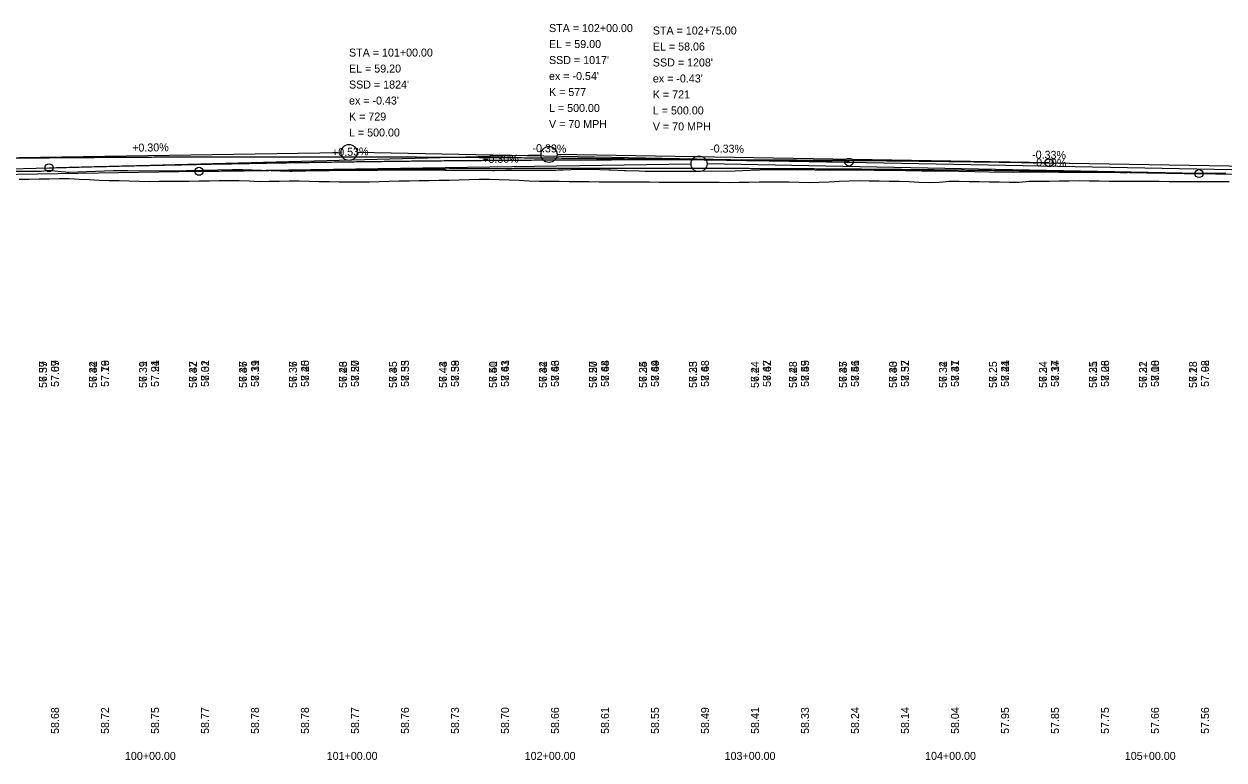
# Model space of a CAD drawing. Extents: x 3880794 to 3915434, y 287517 to 300173.
# Drawn here: x 3890476 to 3891076, y 296520 to 296888 of the extents above; entities that cross this region are included whole.
import ezdxf

# ---------------------------------------------------------------- set-up
doc = ezdxf.new("R2010")
doc.units = 0
for name, color, linetype in [('Level 1', 7, 'Continuous'), ('Level 2', 7, 'Continuous'), ('Level 30', 7, 'Continuous'), ('Level 31', 7, 'Continuous'), ('Level 32', 7, 'Continuous')]:
    doc.layers.add(name, color=color, linetype=linetype)

msp = doc.modelspace()

# ---------------------------------------------------------------- linework, layer by layer
at = {"layer": 'Level 1'}
for p, q in [((3890388.3, 296820.01), (3890634.3, 296823.7)), ((3890488.3, 296816.09), (3890734.3, 296822.65)), ((3890888.3, 296818.94), (3890642.3, 296823.68)), ((3890988.3, 296818.59), (3890742.3, 296822.69)), ((3890438.3, 296814.76), (3890488.3, 296816.09)), ((3890888.3, 296818.94), (3891088.3, 296815.08)), ((3890988.3, 296818.59), (3891088.3, 296816.92))]:
    msp.add_line(p, q, dxfattribs=at)
for points in [[(3890470.64, 296814.38), (3890481.24, 296814.49), (3890481.57, 296814.49), (3890484.41, 296814.33), (3890485.66, 296814.55), (3890487.25, 296814.72), (3890489.34, 296814.66), (3890491.17, 296814.52), (3890494.38, 296814.25), (3890496.56, 296814.04), (3890497.6, 296813.93), (3890498.03, 296813.87), (3890520.48, 296814.73), (3890526.64, 296814.75), (3890527.58, 296814.74), (3890552.38, 296814.64), (3890556.96, 296814.73)], [(3890556.96, 296814.73), (3890558.17, 296814.73), (3890580.05, 296815.22), (3890582.32, 296815.25), (3890585.1, 296815.18), (3890608.88, 296814.47), (3890609.81, 296814.49), (3890615.66, 296814.58), (3890616.57, 296814.56), (3890640.14, 296814.94), (3890641.21, 296814.92), (3890651.51, 296814.96), (3890652.48, 296814.96), (3890676.43, 296815.05), (3890677.22, 296815.06), (3890685.45, 296814.98), (3890686.13, 296815), (3890686.43, 296814.99), (3890710.09, 296814.78), (3890710.44, 296814.79), (3890710.81, 296814.82), (3890716.71, 296814.84), (3890717.43, 296814.85), (3890728.83, 296814.88), (3890729.73, 296814.9), (3890731.14, 296814.94), (3890741.66, 296814.97), (3890743.03, 296815.01), (3890745.42, 296815.06), (3890753.04, 296815.41), (3890759.14, 296815.39), (3890768.18, 296815.06), (3890768.97, 296815.03), (3890775.95, 296814.78), (3890776.75, 296814.71), (3890783.31, 296814.54), (3890786.37, 296814.45), (3890794.24, 296814.42), (3890798.91, 296814.46), (3890805.76, 296814.47), (3890812.3, 296814.49), (3890819.03, 296814.52), (3890827.49, 296814.44), (3890838.93, 296814.96), (3890848.37, 296815.21), (3890862.69, 296815.16), (3890864.24, 296815.19), (3890878.37, 296814.98), (3890886.25, 296815.03), (3890900.83, 296814.83), (3890908.36, 296814.83), (3890908.78, 296814.83), (3890924.72, 296814.64), (3890933.63, 296814.51), (3890934.62, 296814.5), (3890951.3, 296814.31), (3890958.54, 296814.07), (3890970.52, 296813.95), (3890978.52, 296814.02), (3890993.25, 296813.91), (3891001.84, 296813.88), (3891007.06, 296813.85), (3891023.83, 296813.73), (3891027.36, 296813.73), (3891030.67, 296813.85), (3891046.08, 296813.75), (3891051.84, 296813.42), (3891067.15, 296813.41), (3891071.65, 296813.43), (3891076.77, 296813.34)]]:
    msp.add_lwpolyline(points, dxfattribs=at)
for centre in [(3890638.3, 296823.76), (3890738.3, 296822.76)]:
    msp.add_circle(centre, 4, dxfattribs=at)
for points in [[(3890388.3, 296820.01), (3890398.3, 296820.15), (3890408.3, 296820.29), (3890418.3, 296820.43), (3890428.3, 296820.55), (3890438.3, 296820.67), (3890448.3, 296820.78), (3890458.3, 296820.89), (3890468.3, 296820.99), (3890478.3, 296821.08), (3890488.3, 296821.16), (3890498.3, 296821.24), (3890508.3, 296821.31), (3890518.3, 296821.38), (3890528.3, 296821.43), (3890538.3, 296821.49), (3890548.3, 296821.53), (3890558.3, 296821.57), (3890568.3, 296821.6), (3890578.3, 296821.62), (3890588.3, 296821.64), (3890598.3, 296821.64), (3890608.3, 296821.65), (3890618.3, 296821.64), (3890628.3, 296821.63), (3890638.3, 296821.61), (3890648.3, 296821.59), (3890658.3, 296821.56), (3890668.3, 296821.52), (3890678.3, 296821.47), (3890688.3, 296821.42), (3890698.3, 296821.36), (3890708.3, 296821.3), (3890718.3, 296821.22), (3890728.3, 296821.14), (3890738.3, 296821.06), (3890748.3, 296820.96), (3890758.3, 296820.86), (3890768.3, 296820.76), (3890778.3, 296820.64), (3890788.3, 296820.52), (3890798.3, 296820.39), (3890808.3, 296820.26), (3890818.3, 296820.12), (3890828.3, 296819.97), (3890838.3, 296819.81), (3890848.3, 296819.65), (3890858.3, 296819.48), (3890868.3, 296819.31), (3890878.3, 296819.12), (3890888.3, 296818.94)], [(3890488.3, 296816.09), (3890498.3, 296816.35), (3890508.3, 296816.61), (3890518.3, 296816.85), (3890528.3, 296817.09), (3890538.3, 296817.32), (3890548.3, 296817.53), (3890558.3, 296817.74), (3890568.3, 296817.95), (3890578.3, 296818.14), (3890588.3, 296818.32), (3890598.3, 296818.5), (3890608.3, 296818.67), (3890618.3, 296818.82), (3890628.3, 296818.97), (3890638.3, 296819.12), (3890648.3, 296819.25), (3890658.3, 296819.37), (3890668.3, 296819.49), (3890678.3, 296819.59), (3890688.3, 296819.69), (3890698.3, 296819.78), (3890708.3, 296819.86), (3890718.3, 296819.93), (3890728.3, 296819.99), (3890738.3, 296820.05), (3890748.3, 296820.09), (3890758.3, 296820.13), (3890768.3, 296820.16), (3890778.3, 296820.18), (3890788.3, 296820.19), (3890798.3, 296820.19), (3890808.3, 296820.19), (3890818.3, 296820.17), (3890828.3, 296820.15), (3890838.3, 296820.12), (3890848.3, 296820.07), (3890858.3, 296820.02), (3890868.3, 296819.97), (3890878.3, 296819.9), (3890888.3, 296819.82), (3890898.3, 296819.74), (3890908.3, 296819.65), (3890918.3, 296819.54), (3890928.3, 296819.43), (3890938.3, 296819.32), (3890948.3, 296819.19), (3890958.3, 296819.05), (3890968.3, 296818.91), (3890978.3, 296818.75), (3890988.3, 296818.59)]]:
    msp.add_spline(points, degree=3, dxfattribs=at)
at = {"layer": 'Level 2'}
for p, q in [((3890438.3, 296812.46), (3890563.3, 296814.33)), ((3890563.3, 296814.33), (3890809.3, 296818.02)), ((3891063.3, 296813.17), (3890817.3, 296818)), ((3891063.3, 296813.17), (3891088.3, 296812.67))]:
    msp.add_line(p, q, dxfattribs=at)
for points in [[(3890473.3, 296810.35), (3890478.3, 296810.39), (3890483.3, 296810.5), (3890488.3, 296810.61), (3890493.3, 296810.72), (3890498.3, 296810.77), (3890503.3, 296810.47), (3890508.3, 296810.17), (3890513.3, 296809.88), (3890518.3, 296809.79), (3890523.3, 296809.66), (3890528.3, 296809.53), (3890533.3, 296809.4), (3890538.3, 296809.31)], [(3890538.3, 296809.31), (3890543.3, 296809.35), (3890548.3, 296809.4), (3890553.3, 296809.44), (3890558.3, 296809.48), (3890563.3, 296809.59), (3890568.3, 296809.65), (3890573.3, 296809.7), (3890578.3, 296809.75), (3890583.3, 296809.81), (3890588.3, 296809.59), (3890593.3, 296809.25), (3890598.3, 296809.45), (3890603.3, 296809.48), (3890608.3, 296809.57), (3890613.3, 296809.59), (3890618.3, 296809.41), (3890623.3, 296809.32), (3890628.3, 296809.23), (3890633.3, 296809.14), (3890638.3, 296809.07), (3890643.3, 296809.09), (3890648.3, 296809.12), (3890653.3, 296809.2), (3890658.3, 296809.39), (3890663.3, 296809.5), (3890668.3, 296809.61), (3890673.3, 296809.66), (3890678.3, 296809.74), (3890683.3, 296809.83), (3890688.3, 296809.9), (3890693.3, 296810.04), (3890698.3, 296810.22), (3890703.3, 296810.39), (3890708.3, 296810.4), (3890713.3, 296810.26), (3890718.3, 296810.06), (3890723.3, 296809.83), (3890728.3, 296809.62), (3890733.3, 296809.45), (3890738.3, 296809.35), (3890743.3, 296809.33), (3890748.3, 296809.31), (3890753.3, 296809.18), (3890758.3, 296809.16), (3890763.3, 296809.13), (3890768.3, 296809.13), (3890773.3, 296809.13), (3890778.3, 296809.15), (3890783.3, 296809.09), (3890788.3, 296809.02), (3890793.3, 296808.95), (3890798.3, 296808.96), (3890803.3, 296808.96), (3890808.3, 296808.89), (3890813.3, 296808.9), (3890818.3, 296808.9), (3890823.3, 296808.91), (3890828.3, 296808.82), (3890833.3, 296808.89), (3890838.3, 296808.97), (3890843.3, 296809.04), (3890848.3, 296809.15), (3890853.3, 296809.1), (3890858.3, 296809), (3890863.3, 296808.9), (3890868.3, 296808.81), (3890873.3, 296808.9), (3890878.3, 296809.13), (3890883.3, 296809.36), (3890888.3, 296809.6), (3890893.3, 296809.73), (3890898.3, 296809.65), (3890903.3, 296809.56), (3890908.3, 296809.47), (3890913.3, 296809.38), (3890918.3, 296809.31), (3890923.3, 296808.94), (3890928.3, 296808.72), (3890933.3, 296808.87), (3890938.3, 296809.38), (3890943.3, 296809.36), (3890948.3, 296809.29), (3890953.3, 296809.2), (3890958.3, 296809.1), (3890963.3, 296809), (3890968.3, 296808.89), (3890973.3, 296808.95), (3890978.3, 296809.38), (3890983.3, 296809.42), (3890988.3, 296809.46), (3890993.3, 296809.49), (3890998.3, 296809.57), (3891003.3, 296809.66), (3891008.3, 296809.58), (3891013.3, 296809.5), (3891018.3, 296809.43), (3891023.3, 296809.41), (3891028.3, 296809.46), (3891033.3, 296809.41), (3891038.3, 296809.37)], [(3891038.3, 296809.37), (3891043.3, 296809.33), (3891048.3, 296809.28), (3891053.3, 296809.24), (3891058.3, 296809.18), (3891063.3, 296809.16), (3891068.3, 296809.18), (3891073.3, 296809.2), (3891078.3, 296809.21)]]:
    msp.add_lwpolyline(points, dxfattribs=at)
for centre, radius in [((3890813.3, 296818.08), 4), ((3890563.3, 296814.33), 2), ((3891063.3, 296813.17), 2)]:
    msp.add_circle(centre, radius, dxfattribs=at)
msp.add_spline([(3890563.3, 296814.33), (3890573.3, 296814.48), (3890583.3, 296814.62), (3890593.3, 296814.75), (3890603.3, 296814.88), (3890613.3, 296815), (3890623.3, 296815.11), (3890633.3, 296815.21), (3890643.3, 296815.31), (3890653.3, 296815.4), (3890663.3, 296815.49), (3890673.3, 296815.56), (3890683.3, 296815.63), (3890693.3, 296815.7), (3890703.3, 296815.75), (3890713.3, 296815.8), (3890723.3, 296815.84), (3890733.3, 296815.88), (3890743.3, 296815.91), (3890753.3, 296815.93), (3890763.3, 296815.95), (3890773.3, 296815.95), (3890783.3, 296815.95), (3890793.3, 296815.95), (3890803.3, 296815.94), (3890813.3, 296815.92), (3890823.3, 296815.89), (3890833.3, 296815.85), (3890843.3, 296815.81), (3890853.3, 296815.77), (3890863.3, 296815.71), (3890873.3, 296815.65), (3890883.3, 296815.58), (3890893.3, 296815.51), (3890903.3, 296815.42), (3890913.3, 296815.34), (3890923.3, 296815.24), (3890933.3, 296815.14), (3890943.3, 296815.03), (3890953.3, 296814.91), (3890963.3, 296814.79), (3890973.3, 296814.65), (3890983.3, 296814.52), (3890993.3, 296814.37), (3891003.3, 296814.22), (3891013.3, 296814.06), (3891023.3, 296813.9), (3891033.3, 296813.72), (3891043.3, 296813.54), (3891053.3, 296813.36), (3891063.3, 296813.17)], degree=3, dxfattribs=at)
at = {"layer": 'Level 31'}
for centre in [(3890888.3, 296818.94), (3890988.3, 296818.59), (3890488.3, 296816.09)]:
    msp.add_circle(centre, 2, dxfattribs=at)

# ---------------------------------------------------------------- texts
at = {"layer": 'Level 2'}
for s, p in [('STA = 102+75.00', (3890790.22, 296882.8)), ('EL = 58.06', (3890790.22, 296874.8)), ("SSD = 1208'", (3890790.22, 296866.8)), ("ex = -0.43'", (3890790.22, 296858.8)), ('K = 721', (3890790.22, 296850.8)), ('L = 500.00', (3890790.22, 296842.8)), ('V = 70 MPH', (3890790.22, 296834.8)), ('100+00.00', (3890526.27, 296519.76)), ('101+00.00', (3890627.15, 296519.76)), ('102+00.00', (3890726.14, 296519.76)), ('103+00.00', (3890826.11, 296519.76)), ('104+00.00', (3890926.33, 296519.76)), ('105+00.00', (3891026.2, 296519.76))]:
    msp.add_text(s, height=4, dxfattribs=at).set_placement(p)
for s, rotation, p in [('+0.30%', 0.85937, (3890704.9, 296818.46)), ('-0.39%', 358.87333, (3890980.04, 296816.8)), ('57.09', 90, (3890493.3, 296706.43)), ('57.16', 90, (3890518.3, 296706.43)), ('57.24', 90, (3890543.3, 296706.43)), ('57.31', 90, (3890568.3, 296706.43)), ('57.39', 90, (3890593.3, 296706.43)), ('57.45', 90, (3890618.3, 296706.43)), ('57.50', 90, (3890643.3, 296706.43)), ('57.55', 90, (3890668.3, 296706.43)), ('57.58', 90, (3890693.3, 296706.43)), ('57.61', 90, (3890718.3, 296706.43)), ('57.63', 90, (3890743.3, 296706.43)), ('57.64', 90, (3890768.3, 296706.43)), ('57.64', 90, (3890793.3, 296706.43)), ('57.63', 90, (3890818.3, 296706.43)), ('57.62', 90, (3890849.24, 296706.43)), ('57.59', 90, (3890868.3, 296706.43)), ('57.56', 90, (3890893.3, 296706.43)), ('57.52', 90, (3890918.3, 296706.43)), ('57.47', 90, (3890943.3, 296706.43)), ('57.41', 90, (3890968.3, 296706.43)), ('57.34', 90, (3890993.3, 296706.43)), ('57.26', 90, (3891018.3, 296706.43)), ('57.18', 90, (3891043.3, 296706.43)), ('57.08', 90, (3891068.3, 296706.43))]:
    msp.add_text(s, height=4, rotation=rotation, dxfattribs=at).set_placement(p)
at = {"layer": 'Level 30'}
for s, p in [('57.39', (3890487.3, 296705.91)), ('57.34', (3890512.3, 296705.91)), ('57.39', (3890537.3, 296705.91)), ('57.42', (3890562.3, 296705.91)), ('57.46', (3890587.3, 296705.91)), ('57.36', (3890612.3, 296705.91)), ('57.43', (3890637.3, 296705.91)), ('57.45', (3890662.3, 296705.91)), ('57.44', (3890687.3, 296705.91)), ('57.41', (3890712.3, 296705.91)), ('57.44', (3890737.3, 296705.91)), ('57.50', (3890762.3, 296705.91)), ('57.34', (3890787.3, 296705.91)), ('57.35', (3890812.3, 296705.91)), ('57.44', (3890843.24, 296705.91)), ('57.48', (3890862.3, 296705.91)), ('57.45', (3890887.3, 296705.91)), ('57.40', (3890912.3, 296705.91)), ('57.34', (3890937.3, 296705.91)), ('57.25', (3890962.3, 296705.91)), ('57.24', (3890987.3, 296705.91)), ('57.21', (3891012.3, 296705.91)), ('57.21', (3891037.3, 296705.91)), ('57.13', (3891062.3, 296705.91))]:
    msp.add_text(s, height=4, rotation=90, dxfattribs=at).set_placement(p)
for s, p in [('100+00.00', (3890526.27, 296519.76)), ('100+00.00', (3890526.27, 296519.76)), ('100+00.00', (3890526.27, 296519.76)), ('101+00.00', (3890627.15, 296519.76)), ('101+00.00', (3890627.15, 296519.76)), ('101+00.00', (3890627.15, 296519.76)), ('102+00.00', (3890726.14, 296519.76)), ('102+00.00', (3890726.14, 296519.76)), ('102+00.00', (3890726.14, 296519.76)), ('103+00.00', (3890826.11, 296519.76)), ('103+00.00', (3890826.11, 296519.76)), ('103+00.00', (3890826.11, 296519.76)), ('104+00.00', (3890926.33, 296519.76)), ('104+00.00', (3890926.33, 296519.76)), ('104+00.00', (3890926.33, 296519.76)), ('105+00.00', (3891026.2, 296519.76)), ('105+00.00', (3891026.2, 296519.76)), ('105+00.00', (3891026.2, 296519.76))]:
    msp.add_text(s, height=4, dxfattribs=at).set_placement(p)
at = {"layer": 'Level 31'}
for s, p in [('STA = 102+00.00', (3890738.3, 296884.02)), ('EL = 59.00', (3890738.3, 296876.02)), ('STA = 101+00.00', (3890638.3, 296871.76)), ("SSD = 1017'", (3890738.3, 296868.02)), ('EL = 59.20', (3890638.3, 296863.76)), ("ex = -0.54'", (3890738.3, 296860.02)), ("SSD = 1824'", (3890638.3, 296855.76)), ('K = 577', (3890738.3, 296852.02)), ("ex = -0.43'", (3890638.3, 296847.76)), ('L = 500.00', (3890738.3, 296844.02)), ('K = 729', (3890638.3, 296839.76)), ('V = 70 MPH', (3890738.3, 296836.02)), ('L = 500.00', (3890638.3, 296831.76))]:
    msp.add_text(s, height=4, dxfattribs=at).set_placement(p)
for s, rotation, p in [('+0.30%', 0.85937, (3890529.9, 296824.13)), ('+0.53%', 1.52753, (3890629.84, 296821.87)), ('-0.39%', 358.89515, (3890730, 296823.99)), ('-0.33%', 359.04516, (3890818.82, 296823.81)), ('-0.33%', 359.04516, (3890979.81, 296820.73)), ('57.67', 90, (3890493.3, 296706.43)), ('57.79', 90, (3890518.3, 296706.43)), ('57.91', 90, (3890543.3, 296706.43)), ('58.02', 90, (3890568.3, 296706.43)), ('58.11', 90, (3890593.3, 296706.43)), ('58.20', 90, (3890618.3, 296706.43)), ('58.27', 90, (3890643.3, 296706.43)), ('58.33', 90, (3890668.3, 296706.43)), ('58.39', 90, (3890693.3, 296706.43)), ('58.43', 90, (3890718.3, 296706.43)), ('58.46', 90, (3890743.3, 296706.43)), ('58.48', 90, (3890768.3, 296706.43)), ('58.49', 90, (3890793.3, 296706.43)), ('58.48', 90, (3890818.3, 296706.43)), ('58.47', 90, (3890849.24, 296706.43)), ('58.45', 90, (3890868.3, 296706.43)), ('58.41', 90, (3890893.3, 296706.43)), ('58.37', 90, (3890918.3, 296706.43)), ('58.31', 90, (3890943.3, 296706.43)), ('58.24', 90, (3890968.3, 296706.43)), ('58.17', 90, (3890993.3, 296706.43)), ('58.08', 90, (3891018.3, 296706.43)), ('58.00', 90, (3891043.3, 296706.43)), ('57.92', 90, (3891068.3, 296706.43)), ('58.68', 90, (3890493.3, 296532.76)), ('58.72', 90, (3890518.3, 296532.76)), ('58.75', 90, (3890543.3, 296532.76)), ('58.77', 90, (3890568.3, 296532.76)), ('58.78', 90, (3890593.3, 296532.76)), ('58.78', 90, (3890618.3, 296532.76)), ('58.77', 90, (3890643.3, 296532.76)), ('58.76', 90, (3890668.3, 296532.76)), ('58.73', 90, (3890693.3, 296532.76)), ('58.70', 90, (3890718.3, 296532.76)), ('58.66', 90, (3890743.3, 296532.76)), ('58.61', 90, (3890768.3, 296532.76)), ('58.55', 90, (3890793.3, 296532.76)), ('58.49', 90, (3890818.3, 296532.76)), ('58.41', 90, (3890843.3, 296532.76)), ('58.33', 90, (3890868.3, 296532.76)), ('58.24', 90, (3890893.3, 296532.76)), ('58.14', 90, (3890918.3, 296532.76)), ('58.04', 90, (3890943.3, 296532.76)), ('57.95', 90, (3890968.3, 296532.76)), ('57.85', 90, (3890993.3, 296532.76)), ('57.75', 90, (3891018.3, 296532.76)), ('57.66', 90, (3891043.3, 296532.76)), ('57.56', 90, (3891068.3, 296532.76))]:
    msp.add_text(s, height=4, rotation=rotation, dxfattribs=at).set_placement(p)
at = {"layer": 'Level 32'}
for s, p in [('56.57', (3890487.3, 296705.91)), ('56.42', (3890512.3, 296705.91)), ('56.31', (3890537.3, 296705.91)), ('56.37', (3890562.3, 296705.91)), ('56.37', (3890587.3, 296705.91)), ('56.37', (3890612.3, 296705.91)), ('56.26', (3890637.3, 296705.91)), ('56.35', (3890662.3, 296705.91)), ('56.43', (3890687.3, 296705.91)), ('56.50', (3890712.3, 296705.91)), ('56.32', (3890737.3, 296705.91)), ('56.27', (3890762.3, 296705.91)), ('56.25', (3890787.3, 296705.91)), ('56.23', (3890812.3, 296705.91)), ('56.24', (3890843.24, 296705.91)), ('56.23', (3890862.3, 296705.91)), ('56.37', (3890887.3, 296705.91)), ('56.33', (3890912.3, 296705.91)), ('56.32', (3890937.3, 296705.91)), ('56.25', (3890962.3, 296705.91)), ('56.34', (3890987.3, 296705.91)), ('56.35', (3891012.3, 296705.91)), ('56.32', (3891037.3, 296705.91)), ('56.28', (3891062.3, 296705.91))]:
    msp.add_text(s, height=4, rotation=90, dxfattribs=at).set_placement(p)

doc.saveas('drawing.dxf')
